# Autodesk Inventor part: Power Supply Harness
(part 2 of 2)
feature "SweepSrf58" sketch "Sketch58" dims "d57" = 0
workplane "Work Plane59"
sketch "Sketch59"
  geometry: C1 r 0.61 at (0, 0); 1 further point
  constraints: 1 centre point
feature "SweepSrf59" sketch "Sketch59" dims "d58" = 0
workplane "Work Plane60"
sketch "Sketch60"
  geometry: C1 r 0.61 at (0, 0); 1 further point
  constraints: 1 centre point
feature "SweepSrf60" sketch "Sketch60" dims "d59" = 0
workplane "Work Plane61"
sketch "Sketch61"
  geometry: C1 r 0.61 at (0, 0); 1 further point
  constraints: 1 centre point
feature "SweepSrf61" sketch "Sketch61" dims "d60" = 0
workplane "Work Plane62"
sketch "Sketch62"
  geometry: C1 r 0.61 at (0, 0); 1 further point
  constraints: 1 centre point
feature "SweepSrf62" sketch "Sketch62" dims "d61" = 0
workplane "Work Plane63"
sketch "Sketch63"
  geometry: C1 r 0.61 at (0, 0); 1 further point
  constraints: 1 centre point
feature "SweepSrf63" sketch "Sketch63" dims "d62" = 0
workplane "Work Plane64"
sketch "Sketch64"
  geometry: C1 r 0.61 at (0, 0); 1 further point
  constraints: 1 centre point
feature "SweepSrf64" sketch "Sketch64" dims "d63" = 0
workplane "Work Plane65"
sketch "Sketch65"
  geometry: C1 r 0.61 at (0, 0); 1 further point
  constraints: 1 centre point
feature "SweepSrf65" sketch "Sketch65" dims "d64" = 0
workplane "Work Plane66"
sketch "Sketch66"
  geometry: C1 r 0.61 at (0, 0); 1 further point
  constraints: 1 centre point
feature "SweepSrf66" sketch "Sketch66" dims "d65" = 0
workplane "Work Plane67"
sketch "Sketch67"
  geometry: C1 r 0.61 at (0, 0); 1 further point
  constraints: 1 centre point
feature "SweepSrf67" sketch "Sketch67" dims "d66" = 0
workplane "Work Plane68"
sketch "Sketch68"
  geometry: C1 r 0.381 at (0, 0); 1 further point
  constraints: 1 centre point
feature "SweepSrf68" sketch "Sketch68" dims "d67" = 0
workplane "Work Plane69"
sketch "Sketch69"
  geometry: C1 r 0.381 at (0, 0); 1 further point
  constraints: 1 centre point
feature "SweepSrf69" sketch "Sketch69" dims "d68" = 0
workplane "Work Plane70"
sketch "Sketch70"
  geometry: C1 r 0.61 at (0, 0); 1 further point
  constraints: 1 centre point
feature "SweepSrf70" sketch "Sketch70" dims "d69" = 0
workplane "Work Plane71"
sketch "Sketch71"
  geometry: C1 r 0.61 at (0, 0); 1 further point
  constraints: 1 centre point
feature "SweepSrf71" sketch "Sketch71" dims "d70" = 0
workplane "Work Plane72"
sketch "Sketch72"
  geometry: C1 r 0.61 at (0, 0); 1 further point
  constraints: 1 centre point
feature "SweepSrf72" sketch "Sketch72" dims "d71" = 0
workplane "Work Plane73"
sketch "Sketch73"
  geometry: C1 r 0.61 at (0, 0); 1 further point
  constraints: 1 centre point
feature "SweepSrf73" sketch "Sketch73" dims "d72" = 0
workplane "Work Plane74"
sketch "Sketch74"
  geometry: C1 r 0.61 at (0, 0); 1 further point
  constraints: 1 centre point
feature "SweepSrf74" sketch "Sketch74" dims "d73" = 0
workplane "Work Plane75"
sketch "Sketch75"
  geometry: C1 r 0.61 at (0, 0); 1 further point
  constraints: 1 centre point
feature "SweepSrf75" sketch "Sketch75" dims "d74" = 0
workplane "Work Plane76"
sketch "Sketch76"
  geometry: C1 r 0.61 at (0, 0); 1 further point
  constraints: 1 centre point
feature "SweepSrf76" sketch "Sketch76" dims "d75" = 0
workplane "Work Plane77"
sketch "Sketch77"
  geometry: C1 r 0.61 at (0, 0); 1 further point
  constraints: 1 centre point
feature "SweepSrf77" sketch "Sketch77" dims "d76" = 0
workplane "Work Plane78"
sketch "Sketch78"
  geometry: C1 r 0.61 at (0, 0); 1 further point
  constraints: 1 centre point
feature "SweepSrf78" sketch "Sketch78" dims "d77" = 0
workplane "Work Plane79"
sketch "Sketch79"
  geometry: C1 r 0.61 at (0, 0); 1 further point
  constraints: 1 centre point
feature "SweepSrf79" sketch "Sketch79" dims "d78" = 0
workplane "Work Plane80"
sketch "Sketch80"
  geometry: C1 r 0.61 at (0, 0); 1 further point
  constraints: 1 centre point
feature "SweepSrf80" sketch "Sketch80" dims "d79" = 0
workplane "Work Plane81"
sketch "Sketch81"
  geometry: C1 r 0.61 at (0, 0); 1 further point
  constraints: 1 centre point
feature "SweepSrf81" sketch "Sketch81" dims "d80" = 0
workplane "Work Plane82"
sketch "Sketch82"
  geometry: C1 r 0.61 at (0, 0); 1 further point
  constraints: 1 centre point
feature "SweepSrf82" sketch "Sketch82" dims "d81" = 0
workplane "Work Plane83"
sketch "Sketch83"
  geometry: C1 r 0.61 at (0, 0); 1 further point
  constraints: 1 centre point
feature "SweepSrf83" sketch "Sketch83" dims "d82" = 0
workplane "Work Plane84"
sketch "Sketch84"
  geometry: C1 r 0.61 at (0, 0); 1 further point
  constraints: 1 centre point
feature "SweepSrf84" sketch "Sketch84" dims "d83" = 0
workplane "Work Plane85"
sketch "Sketch85"
  geometry: C1 r 0.61 at (0, 0); 1 further point
  constraints: 1 centre point
feature "SweepSrf85" sketch "Sketch85" dims "d84" = 0
workplane "Work Plane86"
sketch "Sketch86"
  geometry: C1 r 0.61 at (0, 0); 1 further point
  constraints: 1 centre point
feature "SweepSrf86" sketch "Sketch86" dims "d85" = 0
workplane "Work Plane87"
sketch "Sketch87"
  geometry: C1 r 0.61 at (0, 0); 1 further point
  constraints: 1 centre point
feature "SweepSrf87" sketch "Sketch87" dims "d86" = 0
workplane "Work Plane88"
sketch "Sketch88"
  geometry: C1 r 0.47 at (0, 0); 1 further point
  constraints: 1 centre point
feature "SweepSrf88" sketch "Sketch88" dims "d87" = 0
workplane "Work Plane89"
sketch "Sketch89"
  geometry: C1 r 0.47 at (0, 0); 1 further point
  constraints: 1 centre point
feature "SweepSrf89" sketch "Sketch89" dims "d88" = 0
workplane "Work Plane90"
sketch "Sketch90"
  geometry: C1 r 0.47 at (0, 0); 1 further point
  constraints: 1 centre point
feature "SweepSrf90" sketch "Sketch90" dims "d89" = 0
workplane "Work Plane91"
sketch "Sketch91"
  geometry: C1 r 0.47 at (0, 0); 1 further point
  constraints: 1 centre point
feature "SweepSrf91" sketch "Sketch91" dims "d90" = 0
workplane "Work Plane92"
sketch "Sketch92"
  geometry: C1 r 0.47 at (0, 0); 1 further point
  constraints: 1 centre point
feature "SweepSrf92" sketch "Sketch92" dims "d91" = 0
workplane "Work Plane93"
sketch "Sketch93"
  geometry: C1 r 0.47 at (0, 0); 1 further point
  constraints: 1 centre point
feature "SweepSrf93" sketch "Sketch93" dims "d92" = 0
workplane "Work Plane94"
sketch "Sketch94"
  geometry: C1 r 0.47 at (0, 0); 1 further point
  constraints: 1 centre point
feature "SweepSrf94" sketch "Sketch94" dims "d93" = 0
workplane "Work Plane95"
sketch "Sketch95"
  geometry: C1 r 0.47 at (0, 0); 1 further point
  constraints: 1 centre point
feature "SweepSrf95" sketch "Sketch95" dims "d94" = 0
workpoint "Work Point227"
body "Srf1"
body "Srf2"
body "Srf3"
body "Srf4"
body "Srf5"
body "Srf6"
body "Srf7"
body "Srf8"
body "Srf9"
body "Srf10"
body "Srf11"
body "Srf12"
body "Srf13"
body "Srf14"
body "Srf15"
body "Srf16"
body "Srf17"
body "Srf18"
body "Srf19"
body "Srf20"
body "Srf21"
body "Srf22"
body "Srf23"
body "Srf24"
body "Srf25"
body "Srf26"
body "Srf27"
body "Srf28"
body "Srf29"
body "Srf30"
body "Srf31"
body "Srf32"
body "Srf33"
body "Srf34"
body "Srf35"
body "Srf36"
body "Srf37"
body "Srf38"
body "Srf39"
body "Srf40"
body "Srf41"
body "Srf42"
body "Srf43"
body "Srf44"
body "Srf45"
body "Srf46"
body "Srf47"
body "Srf48"
body "Srf49"
body "Srf50"
body "Srf51"
body "Srf52"
body "Srf53"
body "Srf54"
body "Srf55"
body "Srf56"
body "Srf57"
body "Srf58"
body "Srf59"
body "Srf60"
body "Srf61"
body "Srf62"
body "Srf63"
body "Srf64"
body "Srf65"
body "Srf66"
body "Srf67"
body "Srf68"
body "Srf69"
body "Srf70"
body "Srf71"
body "Srf72"
body "Srf73"
body "Srf74"
body "Srf75"
body "Srf76"
body "Srf77"
body "Srf78"
body "Srf79"
body "Srf80"
body "Srf81"
body "Srf82"
body "Srf83"
body "Srf84"
body "Srf85"
body "Srf86"
body "Srf87"
body "Srf88"
body "Srf89"
body "Srf90"
body "Srf91"
body "Srf92"
body "Srf93"
body "Srf94"
body "Srf95"
